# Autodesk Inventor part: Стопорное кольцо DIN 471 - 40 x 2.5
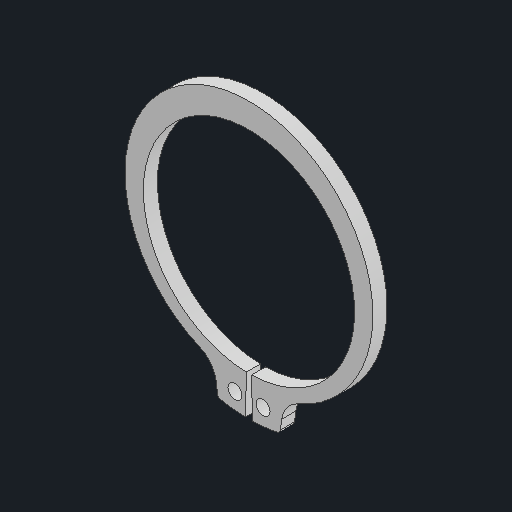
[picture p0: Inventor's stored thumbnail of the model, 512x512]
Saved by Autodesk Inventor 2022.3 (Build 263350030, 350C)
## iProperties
Created: 2020-09
Part Number: Стопорное кольцо DIN 471 - 40 x 2.5
Material: Типовые
Document SubType Name: Modeling
Designer: Карташов
Density: 1 g/cm^3
Appearance: По умолчанию
Title: D:\мои документы\Ирина\_WorldSkills\2020_09 ФНЧ\Module A\Участникам\GIVEN\Стопорное кольцо DIN 471 - 40 x 2.5.stp
Author: Дом
Sending System: Autodesk Inventor 2021
Preprocessor: ST-DEVELOPER v18.1
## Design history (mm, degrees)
feature "Твердое тело2"
node "Твердое тело1"
